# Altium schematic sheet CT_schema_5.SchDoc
size 372 x 245 mm
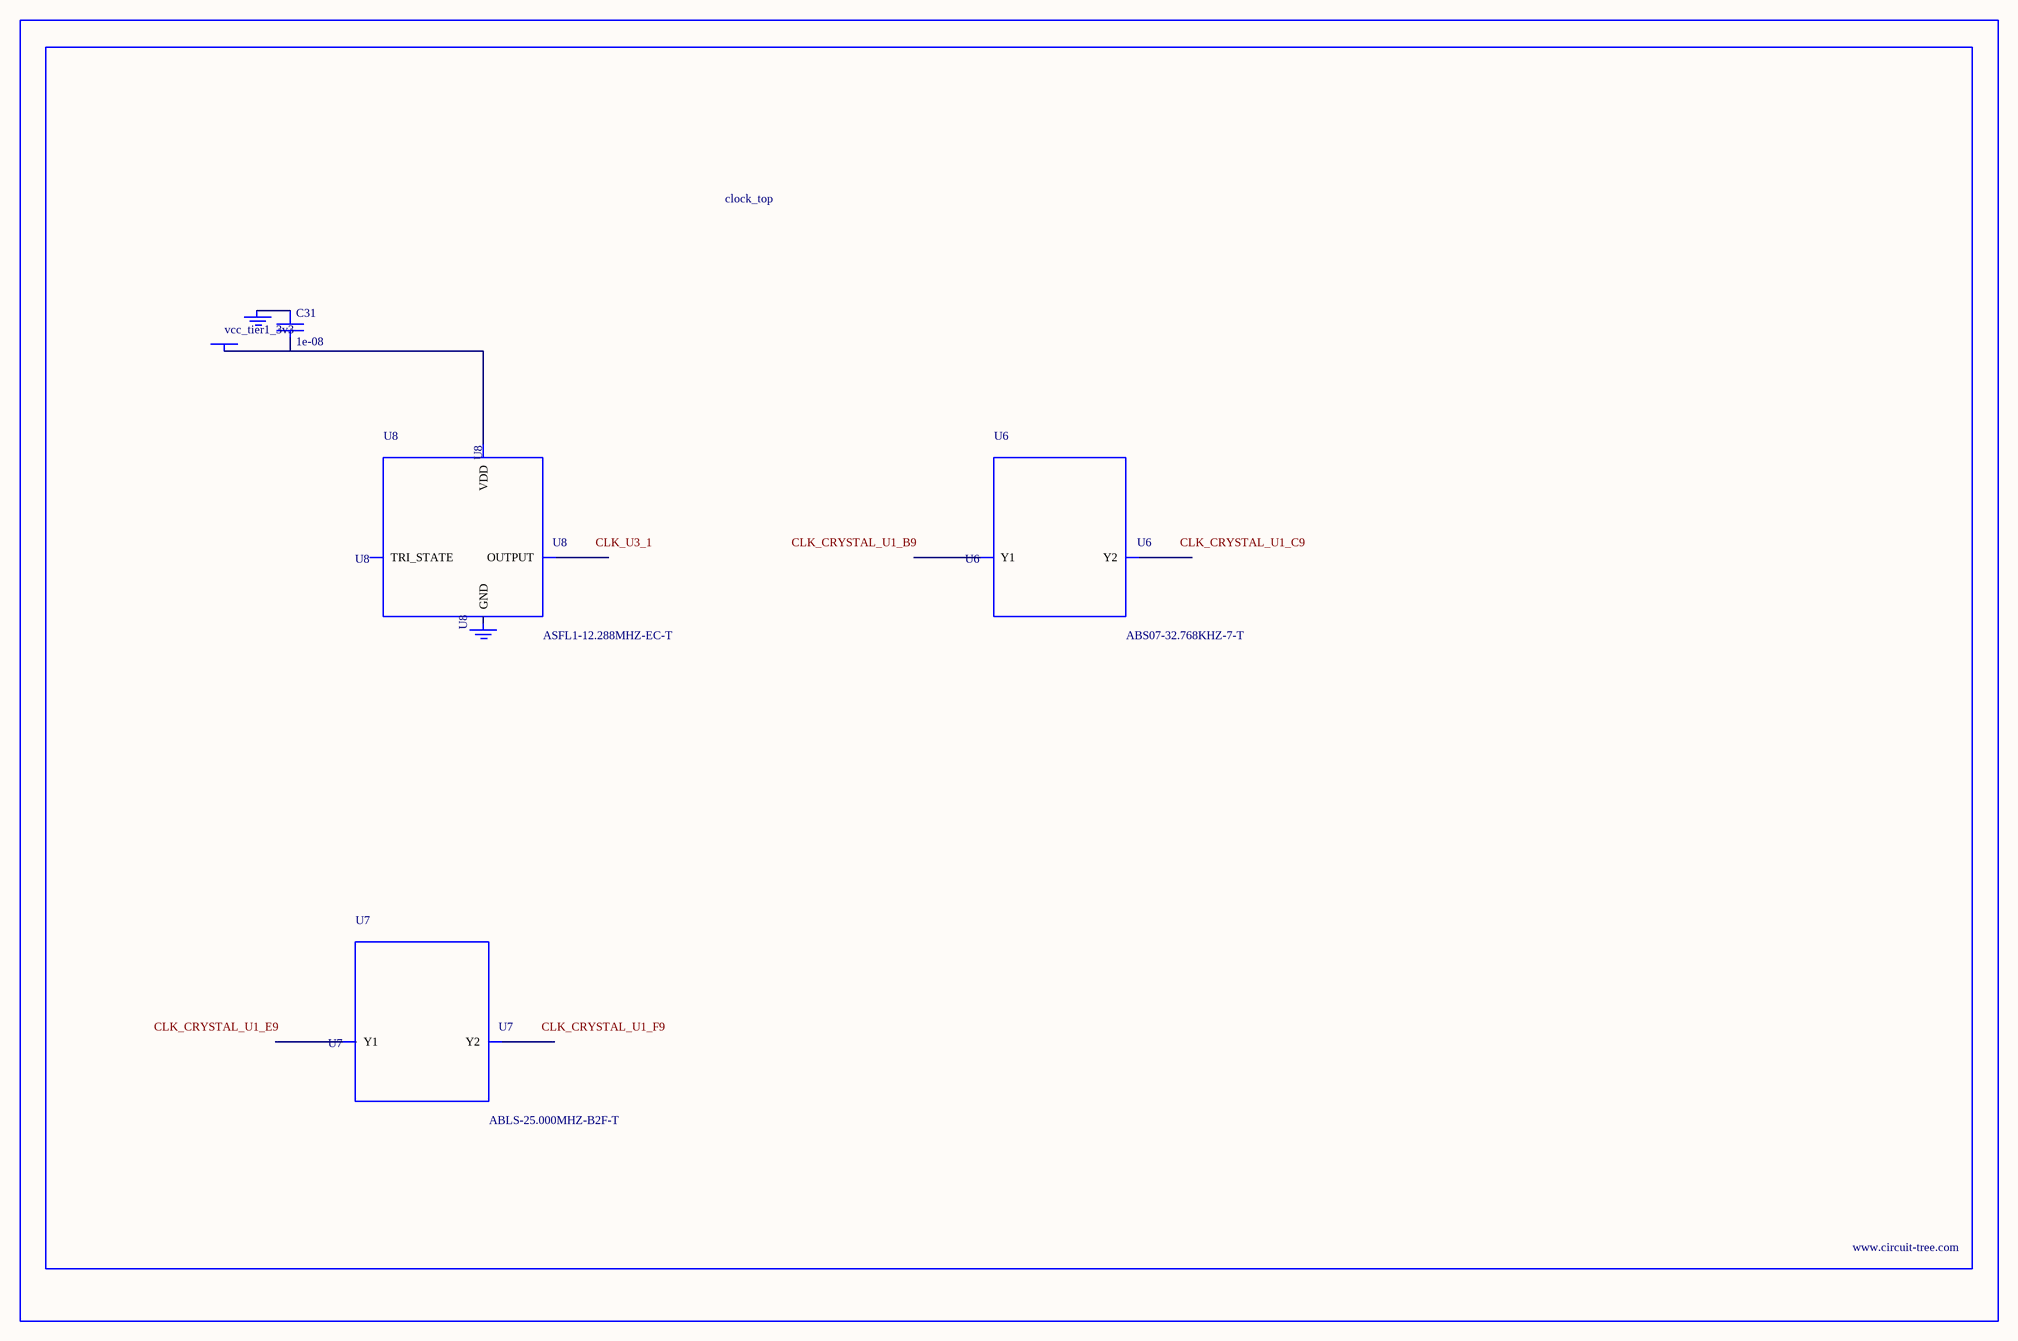
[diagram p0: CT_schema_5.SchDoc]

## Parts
BORDER4  (no value)
C31  1e-08  [C0402]
GND_INSTANCE_4_0  (no value)
GND_INSTANCE_4_1  (no value)
POWER_INSTANCE_4_0  vcc_tier1_3v3
U6  ABS07-32.768KHZ-7-T  [ABS07-32.768KHZ-7-T]
U7  ABLS-25.000MHZ-B2F-T  [ABLS-25.000MHZ-B2F-T]
U8  ASFL1-12.288MHZ-EC-T  [ASFL1]

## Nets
NetC31_1: C31.1 GND_INSTANCE_4_0.0(GND)
NetC31_2: C31.2 POWER_INSTANCE_4_0.0(PWR) U8.4(VDD)

Not connected (* = marked no-connect by the designer): GND_INSTANCE_4_1 0(GND); U6 1(Y1) 2(Y2); U7 1(Y1) 2(Y2); U8 1(TRI_STATE) 2(GND) 3(OUTPUT)

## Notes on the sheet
- Labels drawn without touching a wire or pin: CLK_CRYSTAL_U1_B9, CLK_CRYSTAL_U1_C9, CLK_CRYSTAL_U1_E9, CLK_CRYSTAL_U1_F9, CLK_U3_1

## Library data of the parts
BORDER4 = BORDER_PAGE4
C31 = C0402C103K3RAC
GND_INSTANCE_4_0 GND_INSTANCE_4_1 = GND
POWER_INSTANCE_4_0 = PWR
